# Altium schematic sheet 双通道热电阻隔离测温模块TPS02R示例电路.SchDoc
size A4; CheckedBy: --; Author: lsj; SheetNumber: 1; SheetTotal: 1; PageSetup: Record=PageOptions|CenterHorizontal=True|CenterVertical=True|PrintScale=1.00|XCorrection=1.00|YCorrection=1.00|PrintKind=0|BorderSize=5000000|LeftOffset=0|BottomOffset=0|Orientation=2|PaperLength=1000|PaperWidth=1000|Scale=100|PaperSource=7|PrintQuality=600|MediaType=1|DitherType=10|PaperKind=A4|PrintScaleMode=1; CheckDate: --; SheetName: TPS02R_example; SheetVersion: V1.00; SheetDescription: TPS02R双通道PT100模块示例连接; ModifiedContent1: 初始版本; ModifiedContent2: 修改热电阻输入端管脚排布; ProductName: 双通道PT100隔离测温模块; ProductModel: TPS02R
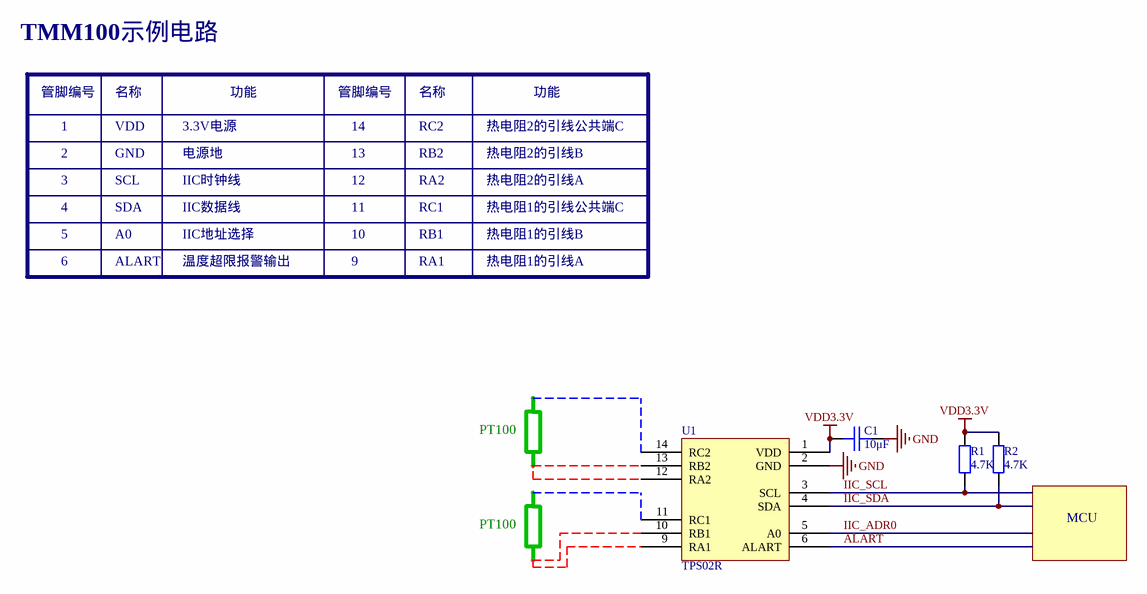
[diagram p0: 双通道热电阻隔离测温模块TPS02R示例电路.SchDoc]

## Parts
C1  10μF  [0805C]
R1  value 4.7K  [AXIAL-0.4]  (hidden comment: Res2)
R2  value 4.7K  [AXIAL-0.4]  (hidden comment: Res2)
U1  TPS02R

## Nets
GND: C1.2 U1.2(GND)
VDD3.3V: C1.1 R1.2 R2.2 U1.1(VDD)
ALART: U1.6(ALART)
IIC_ADR0: U1.5(A0)
IIC_SCL: R1.1 U1.3(SCL)
IIC_SDA: R2.1 U1.4(SDA)

Not connected (* = marked no-connect by the designer): U1 9(RA1) 10(RB1) 11(RC1) 12(RA2) 13(RB2) 14(RC2)

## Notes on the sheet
- TMM100示例电路
- 管脚编号
- 名称
- 功能
- 2
- 1
- 3
- VDD
- GND
- SCL
- 电源地
- 3.3V电源
- IIC时钟线
- 14
- 13
- 12
- RC2
- RB2
- RA2
- 热电阻2的引线A
- 热电阻2的引线B
- 热电阻2的引线公共端C
- 4
- 5
- SDA
- A0
- IIC数据线
- IIC地址选择
- 11
- 10
- RC1
- RB1
- 热电阻1的引线B
- 热电阻1的引线公共端C
- 6
- ALART
- 温度超限报警输出
- 9
- RA1
- 热电阻1的引线A
- PT100
- MCU

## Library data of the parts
C1 = 1.02.02.0055: 106,10μF,±10%,10V,X5R,0805,RoHS; 名称: 电容; 封装: 0805; 设备封装名称: C0805_106_X5R_10V_10%; 贴片和直插: SMT; 器件优选方案: 正常状态，可以选用
R1 R2 = Res2: Resistor
U1 = TCM100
